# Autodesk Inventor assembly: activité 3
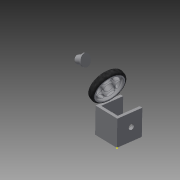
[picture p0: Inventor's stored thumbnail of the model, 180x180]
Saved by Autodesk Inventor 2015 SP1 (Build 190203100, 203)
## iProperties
Created: 2015-01
Part Number: activité 3
Document SubType Name: Assembly
Designer: Dominique
Author: Dominique
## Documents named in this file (4)
- D:\dominique\travail\année 2014-2015\T STI2D\ITEC\itec\activité création de l'arbre\activité 3.iam
- D:\dominique\travail\année 2014-2015\T STI2D\ITEC\itec\corps en U avec butée et rainure anneau elastique.ipt
- D:\dominique\travail\année 2014-2015\T STI2D\ITEC\itec\roue valise.ipt
- D:\dominique\travail\année 2014-2015\T STI2D\ITEC\itec\cimblot roue.ipt
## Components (3 placed, 3 different names)
1. corps en U avec butée et rainure anneau elastique:1 — Affleurement:2
2. roue valise:1
3. cimblot roue:1
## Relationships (1: Flush 1)
- Affleurement:2 [Flush]: corps en U avec butée et rainure anneau elastique:1
